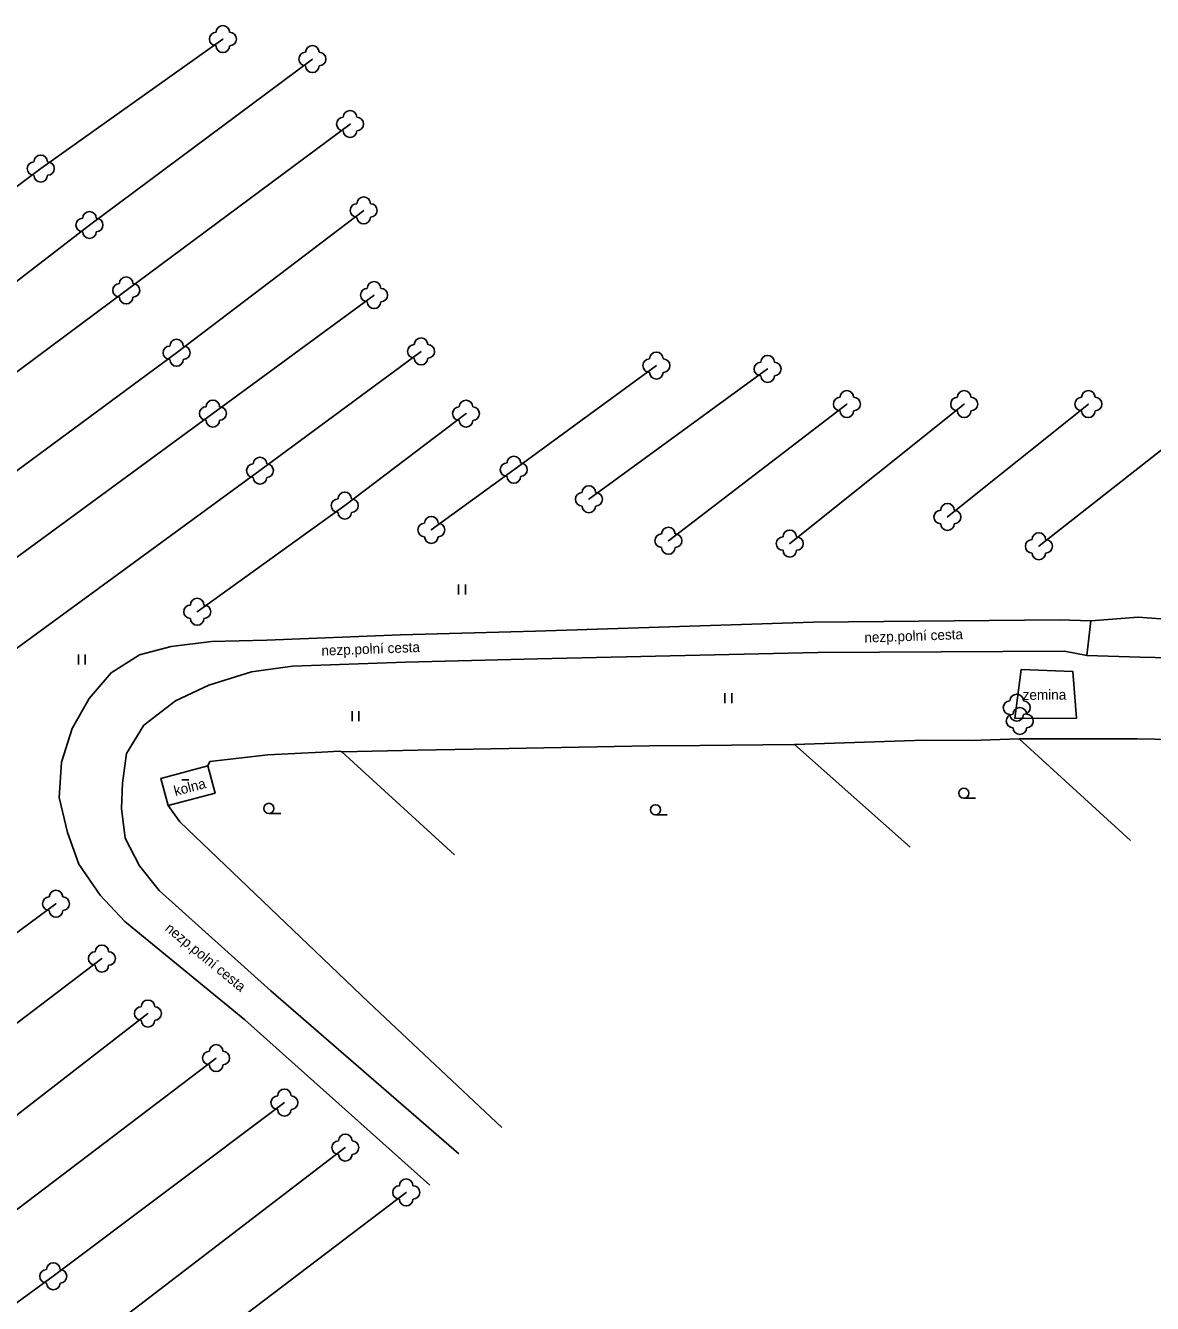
# Model space of a CAD drawing. Extents: x -577457 to -568404, y -1208466 to -1201387.
# Drawn here: x -569434.2 to -569350.8, y -1204305 to -1204210.4 of the extents above; entities that cross this region are included whole.
import ezdxf

# ---------------------------------------------------------------- set-up
doc = ezdxf.new("R2010")
doc.units = 0
for name, color, linetype in [('BUDOVY_MĚŘ', 7, 'Continuous'), ('BUDOVY_NEMĚŘ', 7, 'Continuous'), ('POMOC_POPIS', 7, 'Continuous'), ('ROZHRANÍ_PLOCH', 7, 'Continuous'), ('ZELEŇ', 7, 'Continuous'), ('ZN_BUDOV', 7, 'Continuous'), ('ZN_DOPLŇKOVÉ', 7, 'Continuous'), ('ZN_KULTUR', 7, 'Continuous')]:
    doc.layers.add(name, color=color, linetype=linetype)

msp = doc.modelspace()

# ---------------------------------------------------------------- linework, layer by layer
at = {"layer": 'BUDOVY_MĚŘ'}
msp.add_lwpolyline([(-569423.66, -1204268.12), (-569424.22, -1204266.12), (-569420.73, -1204265.2)], dxfattribs=at)
at = {"layer": 'BUDOVY_NEMĚŘ'}
msp.add_lwpolyline([(-569423.66, -1204268.12), (-569420.2, -1204267.21), (-569420.73, -1204265.2)], dxfattribs=at)
at = {"layer": 'ROZHRANÍ_PLOCH'}
for points in [[(-569355.33, -1204254.46), (-569357.66, -1204254.37), (-569375.86, -1204254.54), (-569396.47, -1204255.21), (-569406.46, -1204255.5), (-569416.37, -1204255.89), (-569420.45, -1204255.99), (-569423.46, -1204256.34), (-569425.8, -1204256.96), (-569427.9, -1204258.29), (-569429.53, -1204260.2), (-569430.77, -1204262.42), (-569431.56, -1204264.91), (-569431.75, -1204267.54), (-569431.14, -1204270.12), (-569430.29, -1204272.48), (-569428.72, -1204274.76), (-569426.88, -1204276.71), (-569418, -1204283.99), (-569404.28, -1204296.24)], [(-569355.62, -1204257.02), (-569355.33, -1204254.46)], [(-569355.33, -1204254.46), (-569351.82, -1204254.19), (-569343.76, -1204254.76), (-569333.79, -1204255.51), (-569326.86, -1204255.64)], [(-569402.13, -1204293.91), (-569416.06, -1204281.84), (-569424.35, -1204274.42), (-569425.79, -1204272.6), (-569426.85, -1204270.54), (-569427.13, -1204268.34), (-569427.05, -1204266.47), (-569426.77, -1204264.28), (-569425.47, -1204262.18), (-569423.14, -1204260.38), (-569420.67, -1204259.21), (-569417.49, -1204258.24), (-569414.45, -1204257.82), (-569406.09, -1204257.51), (-569396.32, -1204257.27), (-569375.56, -1204256.79), (-569357.27, -1204256.7), (-569355.62, -1204257.02)], [(-569325.61, -1204259.08), (-569333.78, -1204258.2), (-569343.82, -1204257.32), (-569351.68, -1204257.15), (-569355.62, -1204257.02)], [(-569360.96, -1204261.68), (-569356.38, -1204261.65), (-569356.66, -1204258.21), (-569360.5, -1204258.06), (-569360.96, -1204261.68)]]:
    msp.add_lwpolyline(points, dxfattribs=at)
at = {"layer": 'ZELEŇ'}
for points in [[(-569419.62, -1204211.37), (-569433.11, -1204220.96), (-569450.22, -1204233.76), (-569472.77, -1204250.79)], [(-569469.14, -1204255.22), (-569449.2, -1204240.32), (-569429.5, -1204225.14), (-569412.99, -1204212.85)], [(-569410.2, -1204217.66), (-569426.78, -1204229.98), (-569446.8, -1204244.88), (-569465.86, -1204259.65)], [(-569462.75, -1204263.94), (-569451.02, -1204255.25), (-569423.05, -1204234.6), (-569409.19, -1204224.06)], [(-569459.33, -1204268.19), (-569445.22, -1204257.32), (-569420.36, -1204239.1), (-569408.42, -1204230.33)], [(-569455.84, -1204272.57), (-569439.43, -1204259.79), (-569416.87, -1204243.33), (-569404.94, -1204234.5)], [(-569404.18, -1204247.72), (-569398.07, -1204243.26), (-569387.51, -1204235.55)], [(-569392.51, -1204245.45), (-569379.27, -1204235.8)], [(-569386.62, -1204248.52), (-569373.4, -1204238.4)], [(-569377.63, -1204248.73), (-569364.71, -1204238.4)], [(-569365.95, -1204246.76), (-569355.51, -1204238.4)], [(-569421.52, -1204253.78), (-569410.59, -1204245.92), (-569401.61, -1204239.11)], [(-569359.18, -1204248.93), (-569346.34, -1204238.85)], [(-569445.52, -1204285.4), (-569431.98, -1204275.4)], [(-569442.04, -1204289.68), (-569428.58, -1204279.46)], [(-569438.82, -1204294.09), (-569425.17, -1204283.53)], [(-569436.03, -1204298.92), (-569420.12, -1204286.83)], [(-569432.18, -1204302.99), (-569415.06, -1204290.13)], [(-569428.84, -1204307.44), (-569410.55, -1204293.46)], [(-569425.75, -1204311.75), (-569406.04, -1204296.78)], [(-569500.04, -1204353.29), (-569488.52, -1204344.74), (-569446.84, -1204313.67), (-569432.18, -1204302.99)]]:
    msp.add_lwpolyline(points, dxfattribs=at)
for centre in [(-569419.62, -1204211.37), (-569412.99, -1204212.85), (-569410.2, -1204217.66), (-569433.11, -1204220.96), (-569409.19, -1204224.06), (-569429.5, -1204225.14), (-569426.78, -1204229.98), (-569408.42, -1204230.33), (-569423.05, -1204234.6), (-569404.94, -1204234.5), (-569387.51, -1204235.55), (-569379.27, -1204235.8), (-569373.4, -1204238.4), (-569364.71, -1204238.4), (-569355.51, -1204238.4), (-569420.36, -1204239.1), (-569401.61, -1204239.11), (-569416.87, -1204243.33), (-569398.07, -1204243.26), (-569410.59, -1204245.92), (-569392.51, -1204245.45), (-569365.95, -1204246.76), (-569404.18, -1204247.72), (-569386.62, -1204248.52), (-569377.63, -1204248.73), (-569359.18, -1204248.93), (-569421.52, -1204253.78), (-569360.82, -1204260.88), (-569360.59, -1204261.87), (-569431.98, -1204275.4), (-569428.58, -1204279.46), (-569425.17, -1204283.53), (-569420.12, -1204286.83), (-569415.06, -1204290.13), (-569410.55, -1204293.46), (-569406.04, -1204296.78), (-569432.18, -1204302.99)]:
    msp.add_circle(centre, 0.0005, dxfattribs=at)
for centre, start, end in [((-569420.12, -1204211.37), 89.99999, 269.99999), ((-569419.62, -1204210.87), 0, 179.99999), ((-569419.12, -1204211.37), 270, 89.99999), ((-569419.62, -1204211.87), 179.99999, 359.99999), ((-569412.99, -1204212.35), 0, 179.99999), ((-569413.49, -1204212.85), 89.99999, 269.99999), ((-569412.49, -1204212.85), 270, 89.99999), ((-569412.99, -1204213.35), 179.99999, 359.99999), ((-569410.2, -1204217.16), 0, 179.99999), ((-569410.7, -1204217.66), 89.99999, 269.99999), ((-569409.7, -1204217.66), 270, 89.99999), ((-569410.2, -1204218.16), 179.99999, 359.99999), ((-569433.61, -1204220.96), 89.99999, 269.99999), ((-569433.11, -1204220.46), 0, 179.99999), ((-569432.61, -1204220.96), 270, 89.99999), ((-569433.11, -1204221.46), 179.99999, 359.99999), ((-569409.19, -1204223.56), 0, 179.99999), ((-569429.5, -1204224.64), 0, 179.99999), ((-569409.69, -1204224.06), 89.99999, 269.99999), ((-569408.69, -1204224.06), 270, 89.99999), ((-569430, -1204225.14), 89.99999, 269.99999), ((-569429, -1204225.14), 270, 89.99999), ((-569409.19, -1204224.56), 179.99999, 359.99999), ((-569429.5, -1204225.64), 179.99999, 359.99999), ((-569426.78, -1204229.48), 0, 179.99999), ((-569427.28, -1204229.98), 89.99999, 269.99999), ((-569426.28, -1204229.98), 270, 89.99999), ((-569408.92, -1204230.33), 89.99999, 269.99999), ((-569408.42, -1204229.83), 0, 179.99999), ((-569407.92, -1204230.33), 270, 89.99999), ((-569426.78, -1204230.48), 179.99999, 359.99999), ((-569408.42, -1204230.83), 179.99999, 359.99999), ((-569423.05, -1204234.1), 0, 179.99999), ((-569404.94, -1204234), 0, 179.99999), ((-569423.55, -1204234.6), 89.99999, 269.99999), ((-569422.55, -1204234.6), 270, 89.99999), ((-569405.44, -1204234.5), 89.99999, 269.99999), ((-569404.44, -1204234.5), 270, 89.99999), ((-569387.51, -1204235.05), 0, 179.99999), ((-569379.27, -1204235.3), 0, 179.99999), ((-569423.05, -1204235.1), 179.99999, 359.99999), ((-569404.94, -1204235), 179.99999, 359.99999), ((-569388.01, -1204235.55), 89.99999, 269.99999), ((-569387.01, -1204235.55), 270, 89.99999), ((-569379.77, -1204235.8), 89.99999, 269.99999), ((-569378.77, -1204235.8), 270, 89.99999), ((-569387.51, -1204236.05), 179.99999, 359.99999), ((-569379.27, -1204236.3), 179.99999, 359.99999), ((-569373.4, -1204237.9), 0, 179.99999), ((-569364.71, -1204237.9), 0, 179.99999), ((-569355.51, -1204237.9), 0, 179.99999), ((-569420.86, -1204239.1), 89.99999, 269.99999), ((-569420.36, -1204238.6), 0, 179.99999), ((-569419.86, -1204239.1), 270, 89.99999), ((-569402.11, -1204239.11), 89.99999, 269.99999), ((-569401.61, -1204238.61), 0, 179.99999), ((-569401.11, -1204239.11), 270, 89.99999), ((-569373.9, -1204238.4), 89.99999, 269.99999), ((-569372.9, -1204238.4), 270, 89.99999), ((-569365.21, -1204238.4), 89.99999, 269.99999), ((-569364.21, -1204238.4), 270, 89.99999), ((-569356.01, -1204238.4), 89.99999, 269.99999), ((-569355.01, -1204238.4), 270, 89.99999), ((-569420.36, -1204239.6), 179.99999, 359.99999), ((-569401.61, -1204239.61), 179.99999, 359.99999), ((-569373.4, -1204238.9), 179.99999, 359.99999), ((-569364.71, -1204238.9), 179.99999, 359.99999), ((-569355.51, -1204238.9), 179.99999, 359.99999), ((-569416.87, -1204242.83), 0, 179.99999), ((-569398.07, -1204242.76), 0, 179.99999), ((-569417.37, -1204243.33), 89.99999, 269.99999), ((-569416.37, -1204243.33), 270, 89.99999), ((-569398.57, -1204243.26), 89.99999, 269.99999), ((-569397.57, -1204243.26), 270, 89.99999), ((-569416.87, -1204243.83), 179.99999, 359.99999), ((-569398.07, -1204243.76), 179.99999, 359.99999), ((-569410.59, -1204245.42), 0, 179.99999), ((-569393.01, -1204245.45), 89.99999, 269.99999), ((-569392.51, -1204244.95), 0, 179.99999), ((-569392.01, -1204245.45), 270, 89.99999), ((-569411.09, -1204245.92), 89.99999, 269.99999), ((-569410.09, -1204245.92), 270, 89.99999), ((-569392.51, -1204245.95), 179.99999, 359.99999), ((-569365.95, -1204246.26), 0, 179.99999), ((-569410.59, -1204246.42), 179.99999, 359.99999), ((-569404.18, -1204247.22), 0, 179.99999), ((-569366.45, -1204246.76), 89.99999, 269.99999), ((-569365.45, -1204246.76), 270, 89.99999), ((-569404.68, -1204247.72), 89.99999, 269.99999), ((-569403.68, -1204247.72), 270, 89.99999), ((-569387.12, -1204248.52), 89.99999, 269.99999), ((-569386.62, -1204248.02), 0, 179.99999), ((-569386.12, -1204248.52), 270, 89.99999), ((-569377.63, -1204248.23), 0, 179.99999), ((-569365.95, -1204247.26), 179.99999, 359.99999), ((-569359.18, -1204248.43), 0, 179.99999), ((-569404.18, -1204248.22), 179.99999, 359.99999), ((-569386.62, -1204249.02), 179.99999, 359.99999), ((-569378.13, -1204248.73), 89.99999, 269.99999), ((-569377.13, -1204248.73), 270, 89.99999), ((-569359.68, -1204248.93), 89.99999, 269.99999), ((-569358.68, -1204248.93), 270, 89.99999), ((-569377.63, -1204249.23), 179.99999, 359.99999), ((-569359.18, -1204249.43), 179.99999, 359.99999), ((-569421.52, -1204253.28), 0, 179.99999), ((-569422.02, -1204253.78), 89.99999, 269.99999), ((-569421.02, -1204253.78), 270, 89.99999), ((-569421.52, -1204254.28), 179.99999, 359.99999), ((-569361.32, -1204260.88), 89.99999, 269.99999), ((-569360.82, -1204260.38), 0, 179.99999), ((-569360.32, -1204260.88), 270, 89.99999), ((-569361.09, -1204261.87), 89.99999, 269.99999), ((-569360.59, -1204261.37), 0, 179.99999), ((-569360.09, -1204261.87), 270, 89.99999), ((-569360.82, -1204261.38), 179.99999, 359.99999), ((-569360.59, -1204262.37), 179.99999, 359.99999), ((-569431.98, -1204274.9), 0, 179.99999), ((-569432.48, -1204275.4), 89.99999, 269.99999), ((-569431.48, -1204275.4), 270, 89.99999), ((-569431.98, -1204275.9), 179.99999, 359.99999), ((-569429.08, -1204279.46), 89.99999, 269.99999), ((-569428.58, -1204278.96), 0, 179.99999), ((-569428.08, -1204279.46), 270, 89.99999), ((-569428.58, -1204279.96), 179.99999, 359.99999), ((-569425.67, -1204283.53), 89.99999, 269.99999), ((-569425.17, -1204283.03), 0, 179.99999), ((-569424.67, -1204283.53), 270, 89.99999), ((-569425.17, -1204284.03), 179.99999, 359.99999), ((-569420.12, -1204286.33), 0, 179.99999), ((-569420.62, -1204286.83), 89.99999, 269.99999), ((-569419.62, -1204286.83), 270, 89.99999), ((-569420.12, -1204287.33), 179.99999, 359.99999), ((-569415.56, -1204290.13), 89.99999, 269.99999), ((-569415.06, -1204289.63), 0, 179.99999), ((-569414.56, -1204290.13), 270, 89.99999), ((-569415.06, -1204290.63), 179.99999, 359.99999), ((-569410.55, -1204292.96), 0, 179.99999), ((-569411.05, -1204293.46), 89.99999, 269.99999), ((-569410.05, -1204293.46), 270, 89.99999), ((-569410.55, -1204293.96), 179.99999, 359.99999), ((-569406.54, -1204296.78), 89.99999, 269.99999), ((-569406.04, -1204296.28), 0, 179.99999), ((-569405.54, -1204296.78), 270, 89.99999), ((-569406.04, -1204297.28), 179.99999, 359.99999), ((-569432.18, -1204302.49), 0, 179.99999), ((-569432.68, -1204302.99), 89.99999, 269.99999), ((-569431.68, -1204302.99), 270, 89.99999), ((-569432.18, -1204303.49), 179.99999, 359.99999)]:
    msp.add_arc(centre, 0.5, start, end, dxfattribs=at)
at = {"layer": 'ZN_BUDOV'}
msp.add_line((-569422.65, -1204266.22), (-569422.15, -1204266.22), dxfattribs=at)
at = {"layer": 'ZN_DOPLŇKOVÉ'}
for points in [[(-569360.65, -1204263.18), (-569364.16, -1204263.31)], [(-569351.9, -1204263.2), (-569360.65, -1204263.18)], [(-569360.65, -1204263.18), (-569352.38, -1204270.71)], [(-569347.91, -1204263.27), (-569351.9, -1204263.2)], [(-569416.29, -1204264.38), (-569412.29, -1204264.18), (-569410.99, -1204264.11)], [(-569410.82, -1204264.16), (-569410.99, -1204264.11)], [(-569405.17, -1204264.04), (-569410.82, -1204264.16)], [(-569410.82, -1204264.16), (-569402.47, -1204271.79)], [(-569405.17, -1204264.04), (-569401.06, -1204263.95)], [(-569388.02, -1204263.72), (-569401.06, -1204263.95)], [(-569388.02, -1204263.72), (-569384.3, -1204263.68)], [(-569377.28, -1204263.62), (-569384.3, -1204263.68)], [(-569367.65, -1204263.29), (-569377.28, -1204263.62)], [(-569377.28, -1204263.62), (-569368.71, -1204271.2)], [(-569364.16, -1204263.31), (-569367.65, -1204263.29)], [(-569416.29, -1204264.38), (-569420.58, -1204264.88), (-569420.73, -1204265.2)], [(-569423.66, -1204268.12), (-569422.81, -1204269.33), (-569408.84, -1204282.68), (-569398.96, -1204291.97)]]:
    msp.add_lwpolyline(points, dxfattribs=at)
at = {"layer": 'ZN_KULTUR'}
for p, q in [((-569402.16, -1204252.505), (-569402.16, -1204251.755)), ((-569401.66, -1204252.505), (-569401.66, -1204251.755)), ((-569430.31, -1204257.685), (-569430.31, -1204256.935)), ((-569429.81, -1204257.685), (-569429.81, -1204256.935)), ((-569382.43, -1204260.555), (-569382.43, -1204259.805)), ((-569381.93, -1204260.555), (-569381.93, -1204259.805)), ((-569410.04, -1204261.885), (-569410.04, -1204261.135)), ((-569409.54, -1204261.885), (-569409.54, -1204261.135)), ((-569364.74, -1204267.595), (-569363.865, -1204267.595)), ((-569416.21, -1204268.715), (-569415.335, -1204268.715)), ((-569387.58, -1204268.815), (-569386.705, -1204268.815))]:
    msp.add_line(p, q, dxfattribs=at)
for centre in [(-569364.74, -1204267.22), (-569416.21, -1204268.34), (-569387.58, -1204268.44)]:
    msp.add_circle(centre, 0.375, dxfattribs=at)

# ---------------------------------------------------------------- texts
at = {"layer": 'POMOC_POPIS'}
for s, rotation, p in [('nezp.polní cesta', 2.00002, (-569372.09, -1204256.06)), ('nezp.polní cesta', 2.12361, (-569412.31, -1204257.03)), ('zemina', 0.37529, (-569360.38, -1204260.31)), ('kolna', 14.73539, (-569423.14, -1204267.43)), ('nezp.polní cesta', 320.6544, (-569423.96, -1204277.33))]:
    msp.add_text(s, height=0.75, rotation=rotation, dxfattribs=at).set_placement(p)

doc.saveas('drawing.dxf')
